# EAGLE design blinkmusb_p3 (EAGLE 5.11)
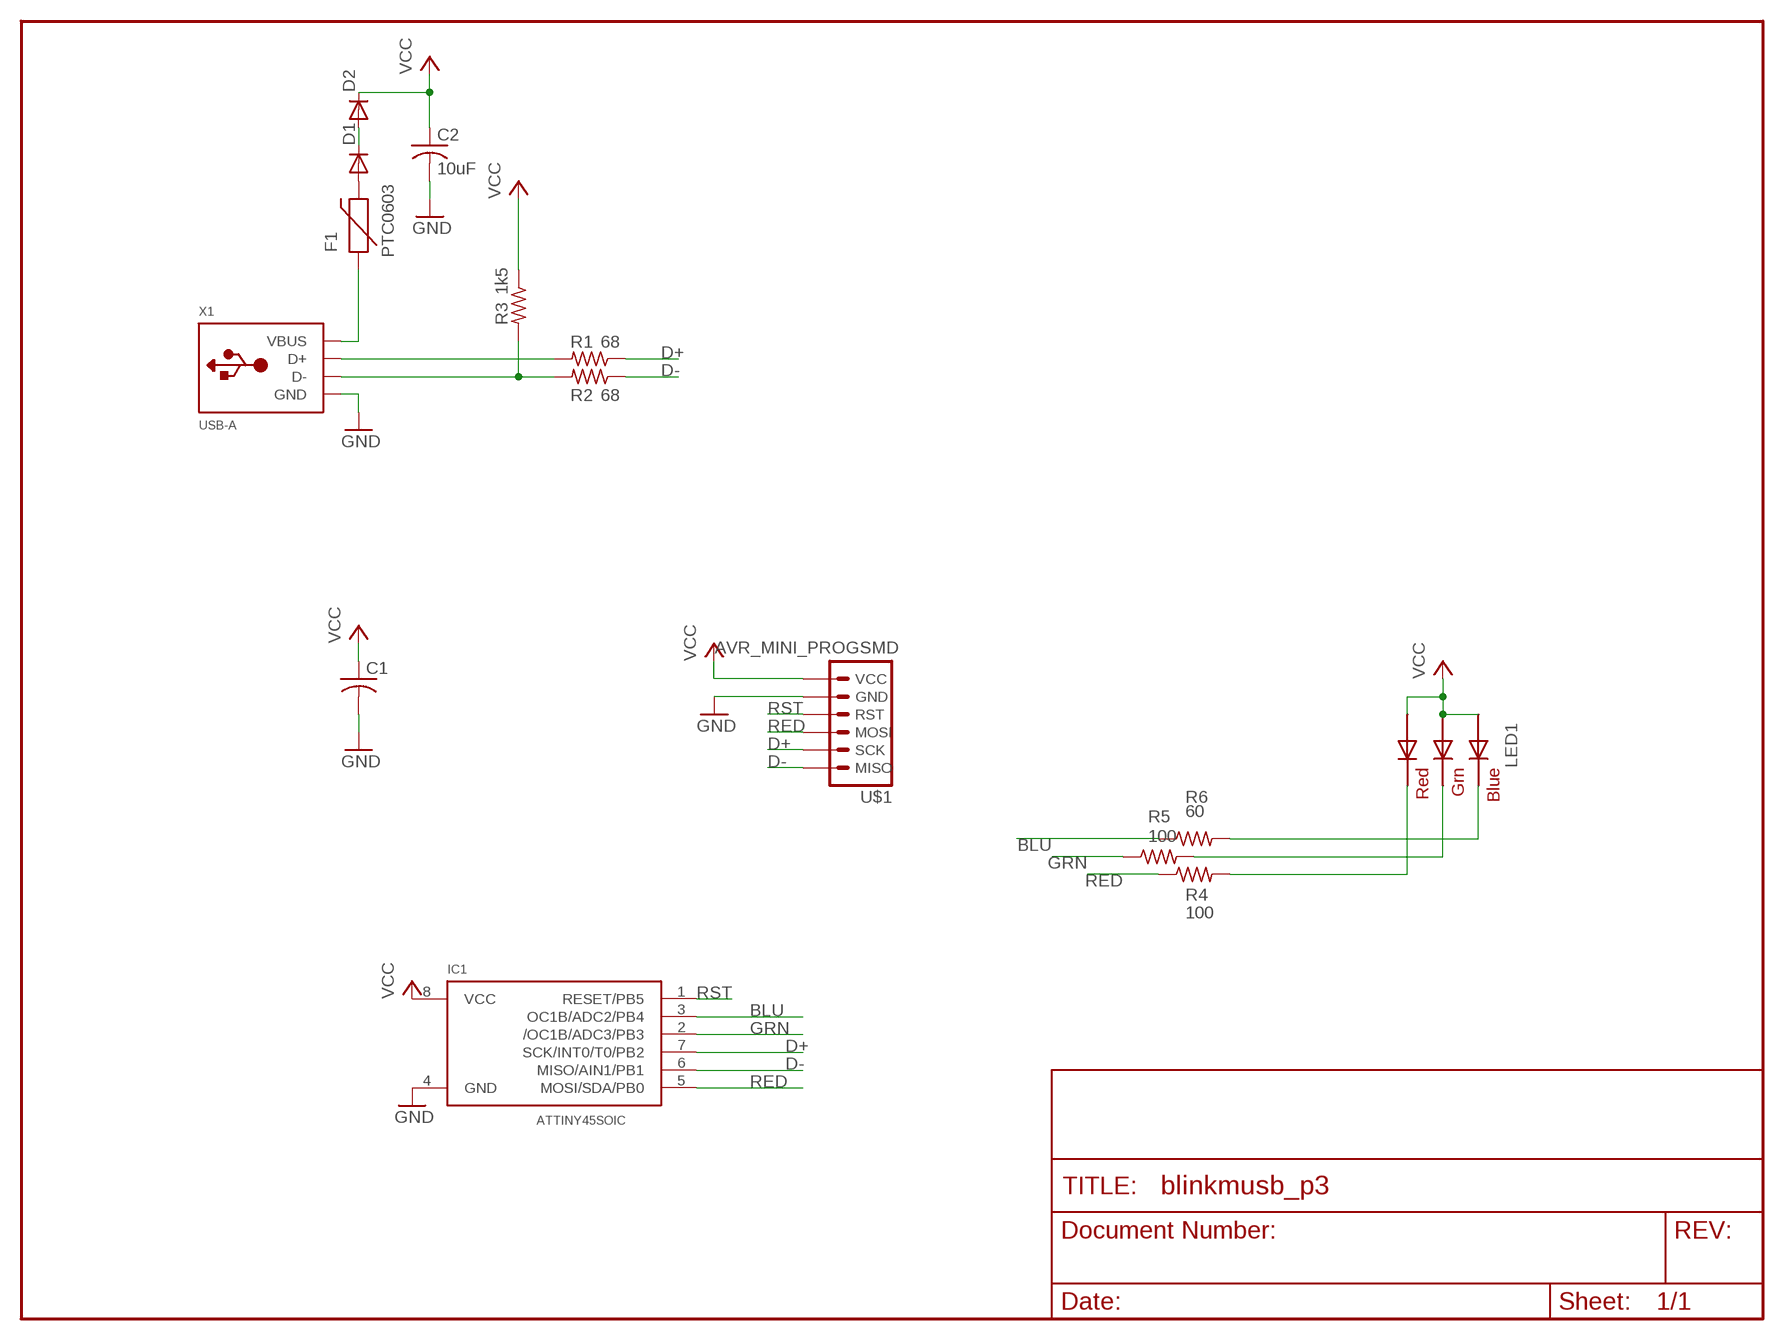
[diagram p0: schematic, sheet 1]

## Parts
C1  C-USC0603  [C0603]
C2  10uF  C-USC0603  [C0603]
D1  DIODESOD  [SOD-323]
D2  DIODESOD  [SOD-323]
F1  PTC0603  [0603]
IC1  ATTINY45SOIC  [SO08-EIAJ]
LED1  RGBLED5050  [RGBLED5050]
R1  68  R-US_R0603  [R0603]
R2  68  R-US_R0603  [R0603]
R3  1k5  R-US_R0603  [R0603]
R4  100  R-US_R0603  [R0603]
R5  100  R-US_R0603  [R0603]
R6  60  R-US_R0603  [R0603]
U$1  AVR_MINI_PROGSMD  [AVR_MINI_PROG]
X1  USB-A  [MOLEX_480371000]

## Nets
BLU: IC1.3(OC1B/ADC2/PB4) R6.1
D+: IC1.7(SCK/INT0/T0/PB2) R1.1 U$1.5(SCK)
D-: IC1.6(MISO/AIN1/PB1) R2.1 U$1.6(MISO)
GND: C1.2 C2.2 IC1.4(GND) U$1.2(GND) X1.4(GND)
GRN: IC1.2(/OC1B/ADC3/PB3) R5.1
N$1: D1.2(A) F1.2
N$4: R1.2 X1.3(D+)
N$5: R2.2 R3.2 X1.2(D-)
N$12: D1.1(C) D2.2(A)
N$13: F1.1 X1.1(VBUS)
RBLU: LED1.4(BLUE_C) R6.2
RED: IC1.5(MOSI/SDA/PB0) R4.1 U$1.4(MOSI)
RGRN: LED1.6(GREEN_C) R5.2
RRED: LED1.5(RED_C) R4.2
RST: IC1.1(RESET/PB5) U$1.3(RST)
VCC: C1.1 C2.1 D2.1(C) IC1.8(VCC) LED1.1(GREEN_A) LED1.2(RED_A) LED1.3(BLUE_A) R3.1 U$1.1(VCC)

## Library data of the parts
C1 C2 = rcl:C-US: CAPACITOR, American symbol
D1 D2 = SparkFun-20110517:DIODE: Diode
F1 = SparkFun-20110517:PTC: Resettable Fuse PTC
IC1 = todstuff:ATTINY45
LED1 = adafruit-20120122:RGBLED: For 5050 RGB LEDs, the order of the LEDs may vary from one manufacturer to another!
R1-R6 = rcl:R-US_: RESISTOR, American symbol
U$1 = SparkFun-20110517:AVR_MINI_PROG
X1 = adafruit-20120122:USB-A: USB type A 'plug' Used for things that can directly connect to a USB port, say USB key

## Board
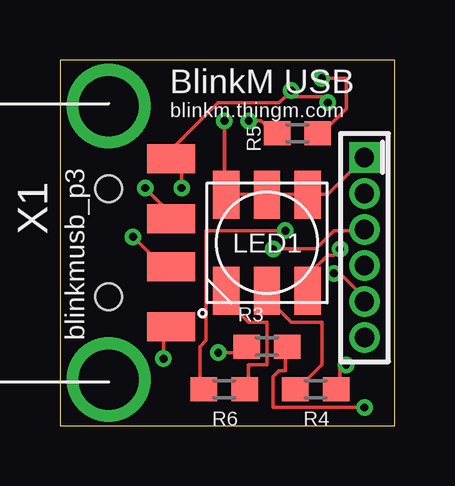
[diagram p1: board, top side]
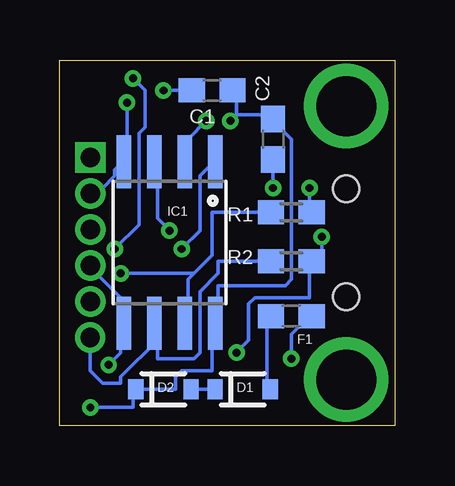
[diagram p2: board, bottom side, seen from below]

Size 13.97 x 15.24 mm. Coordinates in mm from the lower left corner, seen from the top.
Outline: 0,0 13.97,0 13.97,15.24 0,15.24 0,0
Copper layers (1*16): Top 0.0356mm / dielectric 1.5011mm / Bottom 0.0356mm
Design rules "LaenPCBOrder": minimum track width 6mil, minimum drill 13mil, track to track 6mil, track to pad 6mil, pad to pad 6mil, via to via 6mil, smd to smd 6mil, copper to edge 15mil, drill to drill 6mil, minimum pad ring 7mil, minimum via ring 7mil, stop-mask expansion 4mil, vias tented up to drill 0mil, thermal gap 10mil

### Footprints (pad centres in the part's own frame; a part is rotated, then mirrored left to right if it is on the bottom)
C0603 = smd 1.1 x 1: 1 -0.85,0; 2 0.85,0
SOD-323 = smd 0.63 x 0.83: 1 -1.15,0; 2 1.15,0
0603 = smd 1.1 x 1: 1 -0.85,0; 2 0.85,0
SO08-EIAJ = smd 0.61 x 2.21: 1 -1.905,-3.378; 2 -0.635,-3.378; 3 0.635,-3.378; 4 1.905,-3.378; 5 1.905,3.353; 6 0.635,3.353; 7 -0.635,3.353; 8 -1.905,3.353
RGBLED5050 = smd 2 x 1.1: 1 -2,1.7; 2 -2,0; 3 -2,-1.7; 4 2,-1.7; 5 2,0; 6 2,1.7
R0603 = smd 1.1 x 1: 1 -0.85,0; 2 0.85,0
AVR_MINI_PROG = drill 0.8 pad 1.27 square: 1 0,0 | drill 0.8 pad 1.27 round: 2 1.5,0; 3 3,0; 4 4.5,0; 5 6,0; 6 7.5,0.01
MOLEX_480371000 = smd 1.2 x 2: 1 3.5,2.6; 2 1,2.6; 3 -1,2.6; 4 -3.5,2.6 | drill 2.5 round: M1 -5.7,0; M2 5.7,0 | hole 1.1: -2.25,0; 2.25,0

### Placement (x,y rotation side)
C1  7.62,13.97 180 bottom
C2  5.08,11.94 270 bottom
D1  6.35,1.52 0 bottom
D2  9.65,1.52 0 bottom
F1  4.32,4.57 180 bottom
IC1  9.4,7.62 180 bottom
LED1  8.64,7.62 270 top
R1  4.32,8.89 0 bottom
R2  4.32,6.86 0 bottom
R3  8.64,3.3 180 top
R4  10.67,1.52 180 top
R5  9.91,12.19 0 top
R6  6.86,1.52 0 top
U$1  12.7,11.18 270 top
X1  2.03,7.62 270 top

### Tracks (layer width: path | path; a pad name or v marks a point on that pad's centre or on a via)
BLU  (via drill 0.33)
  Top 0.152: v9.4,8.13 6.1,8.13 6.1,3.56 5.84,3.3 5.84,1.52 R6.1
  Bottom 0.152: v9.4,8.13 9.91,8.64 9.91,10.92 IC1.3
D+  (via drill 0.33)
  Top 0.152: v11.43,6.35 11.68,6.35 12.7,5.33 U$1.5
  Bottom 0.152: 8.38,6.35 8.64,6.1 8.64,4.32 IC1.7 | 8.38,6.35 7.62,7.11 7.62,8.89 5.33,8.89 R1.1 | 8.38,6.35 v11.43,6.35
D-
  Bottom 0.152: 9.91,3.56 9.91,4.06 IC1.6 9.91,3.56 | 9.91,3.56 9.91,2.79 8.38,2.79 8.13,3.05 8.13,5.59 7.37,6.35 7.37,6.86 5.33,6.86 R2.1 | 9.91,3.56 11.43,2.03 11.43,1.78 12.19,1.78 12.7,2.29 12.7,3.56 U$1.6
GND  (via drill 0.33)
  Top 0.152: v5.08,9.91 5.08,10.92 4.83,10.92 X1.4 4.83,11.18 4.83,11.68 6.6,13.46 9.14,13.46 9.4,13.72 | 9.4,13.72 v9.65,13.97 | v11.18,13.46 10.92,13.72 9.4,13.72
  Bottom 0.152: U$1.2 12.7,9.91 12.19,9.91 11.68,10.41 11.68,10.67 11.43,10.92 IC1.4 11.18,11.18 v11.18,13.46 | v5.08,9.91 5.08,10.92 C2.2 | v9.65,13.97 8.64,13.97 C1.2
GRN  (via drill 0.33)
  Top 0.152: v7.87,12.7 8.38,12.7 8.89,12.19 R5.1
  Bottom 0.152: v7.87,12.7 8.64,11.94 8.64,11.18 IC1.2
N$1
  Bottom 0.152: D1.2 5.33,1.52 5.33,4.57 F1.2
N$4  (via drill 0.33)
  Top 0.152: v3.56,9.91 4.83,8.64 X1.3
  Bottom 0.152: v3.56,9.91 3.56,8.89 R1.2
N$5  (via drill 0.33)
  Top 0.152: v3.05,7.87 4.06,6.86 4.57,6.86 X1.2 | v6.6,3.05 7.37,3.05 7.62,3.3 R3.2
  Bottom 0.152: v3.05,7.87 3.05,7.11 3.3,6.86 R2.2 3.56,6.86 3.56,5.33 5.84,5.33 6.1,5.08 6.1,3.56 v6.6,3.05
N$12
  Bottom 0.152: D1.1 7.62,1.52 8.38,1.52 D2.2
N$13  (via drill 0.33)
  Top 0.152: v4.32,2.79 4.32,4.06 4.57,4.06 X1.1
  Bottom 0.152: v4.32,2.79 4.32,3.81 3.56,4.57 F1.1
RBLU
  Top 0.152: R6.2 7.87,1.52 7.87,2.54 8.64,2.54 8.64,4.32 7.87,4.32 7.11,5.08 7.11,5.59 LED1.4
RED  (via drill 0.33)
  Top 0.152: v11.94,2.54 11.68,2.54 11.68,1.52 R4.1
  Bottom 0.152: v11.94,2.54 11.43,3.05 11.43,4.06 IC1.5 11.43,4.32 11.43,5.33 12.7,6.6 U$1.4
RGRN  (via drill 0.33)
  Top 0.152: v10.92,14.48 11.94,14.48 11.94,13.21 10.92,12.19 R5.2 | v11.68,7.37 11.43,7.11 11.18,7.11 10.41,6.35 10.41,5.84 LED1.6
  Bottom 0.152: v10.92,14.48 10.41,13.97 10.41,12.45 10.67,12.19 10.67,8.38 v11.68,7.37
RRED
  Top 0.152: R4.2 9.91,1.52 10.92,2.54 10.92,4.32 9.65,4.32 8.64,5.33 8.64,5.59 LED1.5
RST  (via drill 0.33)
  Top 0.152: v8.89,7.37 10.67,7.37 11.43,8.13 12.7,8.13 U$1.3
  Bottom 0.152: v8.89,7.37 8.13,8.13 8.13,10.41 7.62,10.92 IC1.1
VCC  (via drill 0.33)
  Top 0.152: 8.64,9.65 7.11,9.65 LED1.3 6.86,9.65 v6.86,12.7 | 8.64,9.65 LED1.2 8.64,9.65 | 8.64,9.65 10.16,9.65 LED1.1 10.41,9.65 11.18,9.65 U$1.1 | v12.7,0.76 8.89,0.76 8.89,2.03 9.14,2.29 9.4,2.29 9.4,3.3 R3.1
  Bottom 0.152: 6.6,12.95 5.08,12.95 C2.1 5.08,12.7 4.32,11.94 4.32,6.1 4.57,5.84 7.37,5.84 7.37,4.32 IC1.8 7.62,4.06 7.62,2.29 8.89,2.29 9.14,2.03 9.14,1.52 10.67,1.52 D2.1 10.92,1.52 10.92,0.76 v12.7,0.76 | 6.6,12.95 6.6,13.97 C1.1 | 6.6,12.95 v6.86,12.7

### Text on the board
tPlace: BlinkM USB | blinkm.thingm.com | blinkmusb_p3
